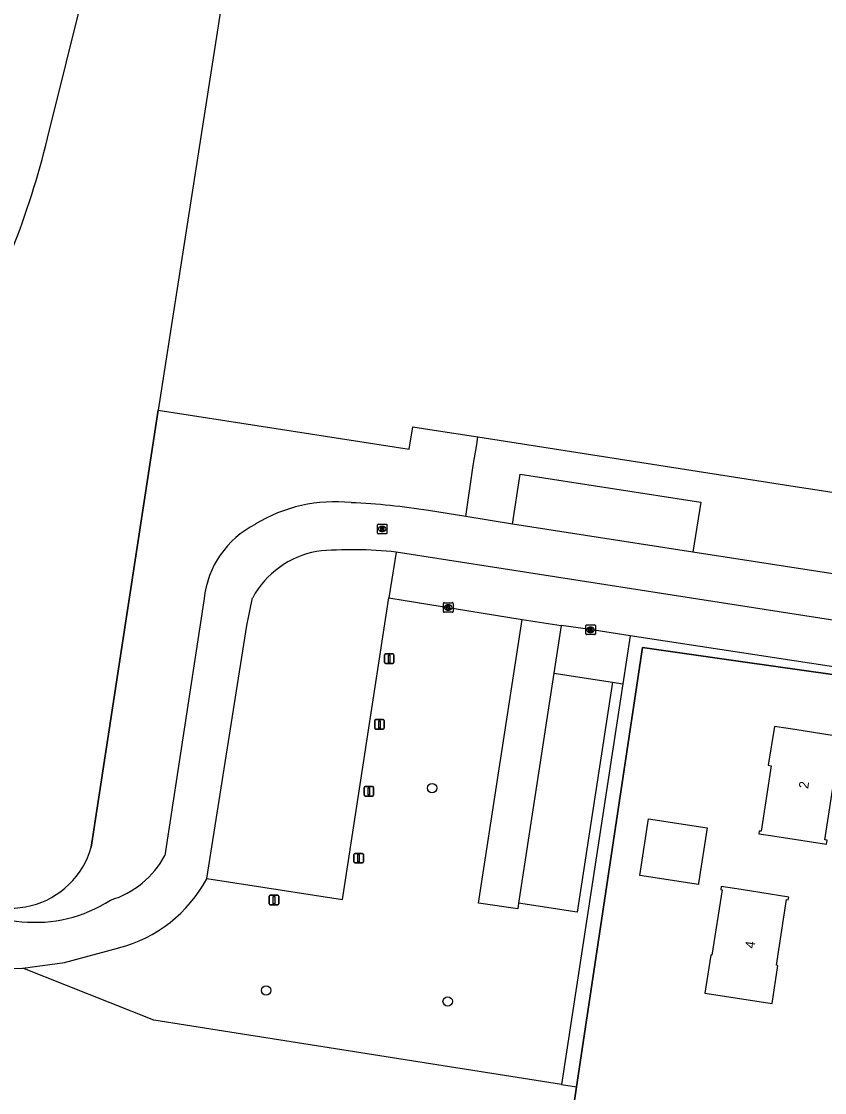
# Model space of a CAD drawing. Extents: x 161094 to 161705, y 379509 to 380907.
# Drawn here: x 161247.8 to 161331.3, y 380505.8 to 380617.3 of the extents above; entities that cross this region are included whole.
import ezdxf

# ---------------------------------------------------------------- set-up
doc = ezdxf.new("R2010")
doc.units = 0
for name, color, linetype in [('IMGEO_Afsluitpaal', 7, 'Continuous'), ('IMGEO_Boom', 7, 'Continuous'), ('IMGEO_Grasland_overig', 7, 'Continuous'), ('IMGEO_Groenvoorziening', 7, 'Continuous'), ('IMGEO_Hek', 7, 'Continuous'), ('IMGEO_Kolk', 7, 'Continuous'), ('IMGEO_Muur', 7, 'Continuous'), ('IMGEO_Pand', 7, 'Continuous'), ('IMGEO_Pand_nummerreeks', 7, 'Continuous'), ('IMGEO_Parkeervlak_open', 7, 'Continuous'), ('IMGEO_Rijbaan_lokaal_gesloten', 7, 'Continuous'), ('IMGEO_Rioolput', 7, 'Continuous'), ('IMGEO_Voetpad_open', 7, 'Continuous')]:
    doc.layers.add(name, color=color, linetype=linetype)

msp = doc.modelspace()

# ---------------------------------------------------------------- linework, layer by layer
at = {"layer": 'IMGEO_Afsluitpaal'}
for p, q in [((161285.57, 380550.57), (161285.57, 380551.37)), ((161285.57, 380551.37), (161285.57, 380550.57)), ((161285.67, 380551.47), (161286.46, 380551.47)), ((161286.46, 380551.47), (161285.67, 380551.47)), ((161286.46, 380550.47), (161285.67, 380550.47)), ((161285.67, 380550.47), (161286.46, 380550.47)), ((161286.56, 380551.37), (161286.56, 380550.57)), ((161286.56, 380550.57), (161286.56, 380551.37)), ((161284.56, 380543.73), (161284.56, 380544.53)), ((161284.56, 380544.53), (161284.56, 380543.73)), ((161284.66, 380544.63), (161285.45, 380544.63)), ((161285.45, 380544.63), (161284.66, 380544.63)), ((161285.55, 380544.53), (161285.55, 380543.73)), ((161285.55, 380543.73), (161285.55, 380544.53)), ((161285.45, 380543.63), (161284.66, 380543.63)), ((161284.66, 380543.63), (161285.45, 380543.63)), ((161283.46, 380536.78), (161283.46, 380537.58)), ((161283.46, 380537.58), (161283.46, 380536.78)), ((161283.56, 380537.68), (161284.35, 380537.68)), ((161284.35, 380537.68), (161283.56, 380537.68)), ((161284.45, 380537.58), (161284.45, 380536.78)), ((161284.45, 380536.78), (161284.45, 380537.58)), ((161284.35, 380536.68), (161283.56, 380536.68)), ((161283.56, 380536.68), (161284.35, 380536.68)), ((161282.39, 380529.82), (161282.39, 380530.61)), ((161282.39, 380530.61), (161282.39, 380529.82)), ((161282.49, 380530.71), (161283.28, 380530.71)), ((161283.28, 380530.71), (161282.49, 380530.71)), ((161283.38, 380530.61), (161283.38, 380529.82)), ((161283.38, 380529.82), (161283.38, 380530.61)), ((161283.28, 380529.72), (161282.49, 380529.72)), ((161282.49, 380529.72), (161283.28, 380529.72)), ((161273.6, 380525.45), (161273.6, 380526.25)), ((161273.6, 380526.25), (161273.6, 380525.45)), ((161273.7, 380526.35), (161274.49, 380526.35)), ((161274.49, 380526.35), (161273.7, 380526.35)), ((161274.59, 380526.25), (161274.59, 380525.45)), ((161274.59, 380525.45), (161274.59, 380526.25)), ((161274.49, 380525.35), (161273.7, 380525.35)), ((161273.7, 380525.35), (161274.49, 380525.35))]:
    msp.add_line(p, q, dxfattribs=at)
for points in [[(161285.99, 380551.34), (161286.14, 380551.34), (161286.14, 380550.59), (161285.99, 380550.59), (161285.99, 380551.34)], [(161284.98, 380544.51), (161285.13, 380544.51), (161285.13, 380543.76), (161284.98, 380543.76), (161284.98, 380544.51)], [(161283.88, 380537.55), (161284.03, 380537.55), (161284.03, 380536.8), (161283.88, 380536.8), (161283.88, 380537.55)], [(161282.81, 380530.59), (161282.96, 380530.59), (161282.96, 380529.84), (161282.81, 380529.84), (161282.81, 380530.59)], [(161274.02, 380526.23), (161274.17, 380526.23), (161274.17, 380525.48), (161274.02, 380525.48), (161274.02, 380526.23)]]:
    msp.add_lwpolyline(points, dxfattribs=at)
for centre, start, end in [((161285.67, 380551.37), 90, 180), ((161285.67, 380551.37), 90, 180), ((161285.67, 380550.57), 180, 270), ((161285.67, 380550.57), 180, 270), ((161286.46, 380551.37), 0, 90), ((161286.46, 380551.37), 360, 90), ((161286.46, 380550.57), 270, 0), ((161286.46, 380550.57), 270, 0), ((161284.66, 380544.53), 90, 180), ((161284.66, 380544.53), 90, 180), ((161285.45, 380544.53), 0, 90), ((161285.45, 380544.53), 360, 90), ((161284.66, 380543.73), 180, 270), ((161284.66, 380543.73), 180, 270), ((161285.45, 380543.73), 270, 0), ((161285.45, 380543.73), 270, 0), ((161283.56, 380537.58), 90, 180), ((161283.56, 380537.58), 90, 180), ((161284.35, 380537.58), 0, 90), ((161284.35, 380537.58), 360, 90), ((161283.56, 380536.78), 180, 270), ((161283.56, 380536.78), 180, 270), ((161284.35, 380536.78), 270, 0), ((161284.35, 380536.78), 270, 0), ((161282.49, 380530.61), 90, 180), ((161282.49, 380530.61), 90, 180), ((161283.28, 380530.61), 0, 90), ((161283.28, 380530.61), 360, 90), ((161282.49, 380529.82), 180, 270), ((161282.49, 380529.82), 180, 270), ((161283.28, 380529.82), 270, 0), ((161283.28, 380529.82), 270, 0), ((161273.7, 380526.25), 90, 180), ((161273.7, 380526.25), 90, 180), ((161274.49, 380526.25), 0, 90), ((161274.49, 380526.25), 360, 90), ((161273.7, 380525.45), 180, 270), ((161273.7, 380525.45), 180, 270), ((161274.49, 380525.45), 270, 0), ((161274.49, 380525.45), 270, 0)]:
    msp.add_arc(centre, 0.1, start, end, dxfattribs=at)
at = {"layer": 'IMGEO_Boom'}
for centre in [(161290.53, 380537.51), (161273.27, 380516.46), (161292.15, 380515.31)]:
    msp.add_circle(centre, 0.489, dxfattribs=at)
at = {"layer": 'IMGEO_Grasland_overig'}
msp.add_lwpolyline([(161262.04, 380576.82), (161255.07, 380531.35)], dxfattribs=at)
msp.add_arc((161246.7, 380533.71), 8.7, 224.1378, 344.2574, dxfattribs=at)
at = {"layer": 'IMGEO_Groenvoorziening'}
for points in [[(161250.53, 380605.13), (161260.44, 380645.01)], [(161305.54, 380506.41), (161312.4, 380552.13), (161322.85, 380550.65), (161335.35, 380548.88)], [(161310.38, 380548.37), (161304, 380506.66)], [(161304, 380506.66), (161261.6, 380513.37), (161247.98, 380518.77)], [(161302.9, 380488.82), (161304.91, 380502.17), (161305.54, 380506.41)], [(161304, 380506.66), (161305.54, 380506.41)]]:
    msp.add_lwpolyline(points, dxfattribs=at)
msp.add_arc((161165.88, 380625.58), 87.09, 330.4397, 346.4164, dxfattribs=at)
at = {"layer": 'IMGEO_Hek'}
for points in [[(161322.85, 380550.65), (161312.4, 380552.13), (161305.54, 380506.41), (161304.91, 380502.17)], [(161335.35, 380548.88), (161322.85, 380550.65)]]:
    msp.add_lwpolyline(points, dxfattribs=at)
at = {"layer": 'IMGEO_Kolk'}
for p, q in [((161291.71, 380555.88), (161291.71, 380556.73)), ((161291.78, 380556.8), (161292.63, 380556.8)), ((161292.22, 380556.02), (161292.19, 380556.02)), ((161292.2, 380556.58), (161292.22, 380556.58)), ((161292.71, 380556.73), (161292.71, 380555.88)), ((161292.63, 380555.8), (161291.78, 380555.8)), ((161306.51, 380553.56), (161306.51, 380554.41)), ((161306.58, 380554.48), (161307.44, 380554.48)), ((161307, 380554.26), (161307.02, 380554.26)), ((161307.51, 380554.41), (161307.51, 380553.56)), ((161307.44, 380553.48), (161306.58, 380553.48)), ((161307.02, 380553.7), (161306.99, 380553.7))]:
    msp.add_line(p, q, dxfattribs=at)
for points in [[(161291.71, 380555.88), (161291.71, 380556.73)], [(161291.78, 380556.8), (161292.63, 380556.8)], [(161292.03, 380556.5), (161292.15, 380556.5), (161292.15, 380556.35), (161292.28, 380556.5), (161292.45, 380556.5), (161292.3, 380556.35), (161292.45, 380556.1), (161292.3, 380556.1), (161292.22, 380556.27), (161292.15, 380556.2), (161292.15, 380556.1), (161292.03, 380556.1), (161292.03, 380556.5)], [(161292.71, 380556.73), (161292.71, 380555.88)], [(161292.63, 380555.8), (161291.78, 380555.8)], [(161306.51, 380553.56), (161306.51, 380554.41)], [(161306.58, 380554.48), (161307.44, 380554.48)], [(161306.83, 380554.18), (161306.95, 380554.18), (161306.95, 380554.03), (161307.08, 380554.18), (161307.25, 380554.18), (161307.1, 380554.03), (161307.25, 380553.78), (161307.1, 380553.78), (161307.02, 380553.95), (161306.95, 380553.88), (161306.95, 380553.78), (161306.83, 380553.78), (161306.83, 380554.18)], [(161307.51, 380554.41), (161307.51, 380553.56)], [(161307.44, 380553.48), (161306.58, 380553.48)]]:
    msp.add_lwpolyline(points, dxfattribs=at)
for centre, start, end in [((161291.78, 380556.73), 91.552, 178.448), ((161291.78, 380556.73), 91.552, 178.448), ((161292.63, 380556.73), 1.552, 88.448), ((161292.63, 380556.73), 1.552, 88.448), ((161291.78, 380555.88), 181.552, 268.448), ((161291.78, 380555.88), 181.552, 268.448), ((161292.63, 380555.88), 271.552, 358.448), ((161292.63, 380555.88), 271.552, 358.448), ((161306.59, 380554.41), 91.552, 178.448), ((161306.59, 380554.41), 91.552, 178.448), ((161307.43, 380554.41), 1.552, 88.448), ((161307.43, 380554.41), 1.552, 88.448), ((161306.59, 380553.56), 181.552, 268.448), ((161306.59, 380553.56), 181.552, 268.448), ((161307.43, 380553.56), 271.552, 358.448), ((161307.43, 380553.56), 271.552, 358.448)]:
    msp.add_arc(centre, 0.0765, start, end, dxfattribs=at)
for centre, major_axis, ratio, start_param, end_param in [((161292.19, 380556.3), (-0.387, 0.002), 0.722429, 4.712389, 7.853982), ((161292.22, 380556.3), (-0.39, 0.002), 0.717154, 1.570796, 4.712389), ((161307, 380553.98), (-0.387, 0.002), 0.722429, 4.712389, 7.853982), ((161307.02, 380553.98), (-0.39, 0.002), 0.717154, 1.570796, 4.712389)]:
    msp.add_ellipse(centre, major_axis=major_axis, ratio=ratio, start_param=start_param, end_param=end_param, dxfattribs=at)
at = {"layer": 'IMGEO_Muur'}
msp.add_lwpolyline([(161255.07, 380531.35), (161262.04, 380576.82)], dxfattribs=at)
msp.add_arc((161246.7, 380533.71), 8.7, 224.1378, 344.2574, dxfattribs=at)
at = {"layer": 'IMGEO_Pand'}
for points in [[(161278.39, 380639.87), (161272.02, 380640.85), (161262.04, 380576.82)], [(161262.04, 380576.82), (161288.16, 380572.76), (161288.53, 380575.11), (161290.75, 380574.76), (161295.3, 380574.05)], [(161295.3, 380574.05), (161328.27, 380568.89), (161330.59, 380568.53), (161338.54, 380567.28), (161338.68, 380567.26)], [(161303.18, 380549.47), (161299.51, 380525.52)], [(161303.18, 380549.47), (161309.29, 380548.54)], [(161309.29, 380548.54), (161305.63, 380524.59), (161299.51, 380525.52)], [(161324.49, 380532.76), (161325.49, 380532.61), (161326.61, 380532.43), (161331.55, 380531.67), (161331.61, 380532.08), (161331.36, 380532.11), (161332.41, 380538.85), (161332.58, 380538.83), (161333.2, 380542.82), (161328.26, 380543.59), (161326.12, 380543.92), (161325.49, 380539.88), (161325.8, 380539.83), (161324.74, 380533.01), (161324.54, 380533.04), (161324.49, 380532.76)], [(161318.25, 380527.62), (161318.23, 380527.48), (161312.14, 380528.41), (161313.05, 380534.3), (161319.13, 380533.37), (161318.25, 380527.62)], [(161324.6, 380526.64), (161322.68, 380526.94), (161320.59, 380527.26), (161320.54, 380526.95), (161320.68, 380526.93), (161319.62, 380520.12), (161319.51, 380520.14), (161318.9, 380516.16), (161325.89, 380515.08), (161326.5, 380519.06), (161326.33, 380519.09), (161327.39, 380525.9), (161327.57, 380525.87), (161327.62, 380526.17), (161324.6, 380526.64)]]:
    msp.add_lwpolyline(points, dxfattribs=at)
at = {"layer": 'IMGEO_Parkeervlak_open'}
for points in [[(161286.78, 380562.06), (161286.02, 380557.3)], [(161267.1, 380528.09), (161281.23, 380525.9), (161286.02, 380557.3)], [(161286.02, 380557.3), (161299.89, 380555.06)], [(161335.47, 380549.63), (161311.14, 380553.36)]]:
    msp.add_lwpolyline(points, dxfattribs=at)
at = {"layer": 'IMGEO_Rijbaan_lokaal_gesloten'}
for points in [[(161294.03, 380565.76), (161290.16, 380566.39)], [(161298.89, 380564.96), (161294.03, 380565.76)], [(161317.65, 380562.05), (161298.89, 380564.96)], [(161336.2, 380554.34), (161286.78, 380562.06)], [(161336.93, 380559.06), (161317.65, 380562.05)], [(161266.82, 380557.23), (161262.73, 380530.49)], [(161267.1, 380528.09), (161271.28, 380554.44), (161271.87, 380557.32)], [(161247.98, 380518.77), (161252.31, 380519.35), (161257.94, 380520.89)]]:
    msp.add_lwpolyline(points, dxfattribs=at)
for centre, radius, start, end in [((161280.41, 380551.5), 15.8, 83.7847, 121.5946), ((161279.05, 380497.05), 70.22, 80.8965, 87.4874), ((161276.63, 380556.17), 9.86, 117.0937, 173.8585), ((161280.24, 380552.77), 9.52, 100.4566, 151.4779), ((161282.28, 380521.61), 40.7, 83.6504, 95.3102), ((161254.4, 380534.86), 9.4, 286.709, 332.2817), ((161249.25, 380538.04), 14.5, 226.2179, 302.8013), ((161254.35, 380534.9), 14.46, 284.3594, 331.8744), ((161246.88, 380530.17), 11.45, 199.3827, 275.5044)]:
    msp.add_arc(centre, radius, start, end, dxfattribs=at)
at = {"layer": 'IMGEO_Rioolput'}
for p, q in [((161284.92, 380564.97), (161285.77, 380564.97)), ((161284.84, 380564.04), (161284.84, 380564.89)), ((161285.77, 380563.97), (161284.92, 380563.97)), ((161285.33, 380564.75), (161285.36, 380564.75)), ((161285.35, 380564.19), (161285.33, 380564.19)), ((161285.84, 380564.89), (161285.84, 380564.04))]:
    msp.add_line(p, q, dxfattribs=at)
for points in [[(161284.92, 380564.97), (161285.77, 380564.97)], [(161284.84, 380564.04), (161284.84, 380564.89)], [(161285.77, 380563.97), (161284.92, 380563.97)], [(161285.43, 380564.66), (161285.18, 380564.67), (161285.18, 380564.27)], [(161285.18, 380564.27), (161285.3, 380564.27), (161285.3, 380564.43), (161285.32, 380564.43)], [(161285.36, 380564.59), (161285.3, 380564.59), (161285.3, 380564.5)], [(161285.3, 380564.5), (161285.36, 380564.5)], [(161285.36, 380564.4), (161285.43, 380564.27), (161285.57, 380564.27), (161285.51, 380564.39)], [(161285.84, 380564.89), (161285.84, 380564.04)]]:
    msp.add_lwpolyline(points, dxfattribs=at)
for centre, radius, start, end in [((161284.92, 380564.89), 0.0765, 91.552, 178.448), ((161284.92, 380564.89), 0.0765, 91.552, 178.448), ((161285.77, 380564.89), 0.0765, 1.552, 88.448), ((161285.77, 380564.89), 0.0765, 1.552, 88.448), ((161284.92, 380564.04), 0.0765, 181.552, 268.448), ((161284.92, 380564.04), 0.0765, 181.552, 268.448), ((161285.31, 380564.38), 0.0533, 26.0293, 88.6989), ((161285.36, 380564.49), 0.0964, 77.0061, 93.1865), ((161285.34, 380564.69), 0.19, 274.7715, 282.9687), ((161285.38, 380564.55), 0.0378, 276.6634, 79.6772), ((161285.43, 380564.56), 0.109, 350.3612, 89.416), ((161285.43, 380564.55), 0.112, 277.5842, 350.9817), ((161285.41, 380564.34), 0.108, 29.5134, 73.7905), ((161285.77, 380564.04), 0.0765, 271.552, 358.448), ((161285.77, 380564.04), 0.0765, 271.552, 358.448)]:
    msp.add_arc(centre, radius, start, end, dxfattribs=at)
for centre, major_axis, ratio, start_param, end_param in [((161285.33, 380564.47), (-0.387, 0.002), 0.722429, 4.712389, 7.853982), ((161285.35, 380564.47), (-0.39, 0.002), 0.717154, 1.570796, 4.712389)]:
    msp.add_ellipse(centre, major_axis=major_axis, ratio=ratio, start_param=start_param, end_param=end_param, dxfattribs=at)
at = {"layer": 'IMGEO_Voetpad_open'}
for points in [[(161294.03, 380565.76), (161294.81, 380571.09), (161295.17, 380573.26), (161295.3, 380574.05)], [(161298.89, 380564.96), (161299.69, 380570.17), (161318.46, 380567.26), (161317.65, 380562.05)], [(161299.51, 380525.52), (161299.45, 380524.93), (161295.37, 380525.55), (161299.89, 380555.06)], [(161299.89, 380555.06), (161303.95, 380554.44)], [(161303.95, 380554.44), (161303.18, 380549.47)], [(161311.14, 380553.36), (161306.71, 380554.04), (161303.95, 380554.44)], [(161311.14, 380553.36), (161310.38, 380548.37)], [(161309.29, 380548.54), (161310.38, 380548.37)]]:
    msp.add_lwpolyline(points, dxfattribs=at)

# ---------------------------------------------------------------- texts
at = {"layer": 'IMGEO_Pand_nummerreeks'}
for s, rotation, p in [('2', 81.1772, (161329.63, 380537.39)), ('4', 81.1781, (161324.04, 380520.77))]:
    msp.add_text(s, height=1, rotation=rotation, dxfattribs=at).set_placement(p)

doc.saveas('drawing.dxf')
